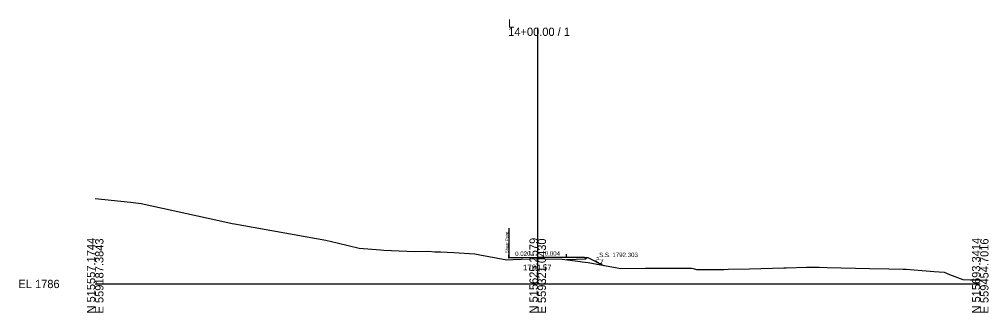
# Model space of a CAD drawing. Extents: x -26 to 1303, y -10 to 9545.
# Drawn here: x 974.3 to 1302.8, y 990.3 to 1089.6 of the extents above; entities that cross this region are included whole.
import ezdxf

# ---------------------------------------------------------------- set-up
doc = ezdxf.new("R2010")
doc.units = 0
for name, color, linetype in [('Exist Cross Section Cell', 7, 'Continuous'), ('Exist XS Center Line Elevation Label', 7, 'Continuous'), ('Exist XS Ground Line', 7, 'Continuous'), ('Prop XS Ditch Slope Text', 7, 'Continuous'), ('Prop XS Dump Level', 7, 'Continuous'), ('Prop XS EOT Tick Mark', 7, 'Continuous'), ('Prop XS Finish Grade', 7, 'Continuous'), ('Prop XS Finish Grade Earthwork', 7, 'Continuous'), ('Prop XS Finish Grade Paved Shoulder', 7, 'Continuous'), ('Prop XS Finish Grade Pavement', 7, 'Continuous'), ('Prop XS Pvmt Edge Slope', 7, 'Continuous'), ('Prop XS SE Text', 7, 'Continuous'), ('Prop XS Shear Point Label', 7, 'Continuous'), ('Prop XS SS Elevation Text', 7, 'Continuous'), ('Prop XS Subgrade Earthwork', 7, 'Continuous')]:
    doc.layers.add(name, color=color, linetype=linetype)

msp = doc.modelspace()

# ---------------------------------------------------------------- linework, layer by layer
at = {"layer": 'Exist Cross Section Cell'}
for p, q in [((1150, 1000), (1150, 1086.75)), ((1000, 1000), (1150, 1000)), ((1150, 1000), (1300, 1000))]:
    msp.add_line(p, q, dxfattribs=at)
at = {"layer": 'Exist XS Ground Line'}
for p, q in [((1000, 1028.92), (1011.97, 1027.67)), ((1011.97, 1027.67), (1015.62, 1027.19)), ((1015.62, 1027.19), (1041.86, 1021.5)), ((1041.86, 1021.5), (1046.44, 1020.5)), ((1046.44, 1020.5), (1047.27, 1020.34)), ((1047.27, 1020.34), (1078.22, 1014.87)), ((1078.22, 1014.87), (1082.07, 1013.97)), ((1082.07, 1013.97), (1089.48, 1012.15)), ((1089.48, 1012.15), (1096.66, 1011.53)), ((1096.66, 1011.53), (1097.82, 1011.47)), ((1097.82, 1011.47), (1108.2, 1010.99)), ((1108.2, 1010.99), (1112.94, 1011.05)), ((1112.94, 1011.05), (1115.15, 1010.92)), ((1115.15, 1010.92), (1117, 1010.85)), ((1117, 1010.85), (1121.56, 1010.62)), ((1121.56, 1010.62), (1128.7, 1010.22)), ((1128.7, 1010.22), (1130.41, 1009.9)), ((1130.41, 1009.9), (1139.56, 1008.22)), ((1139.56, 1008.22), (1141.69, 1008.33)), ((1141.69, 1008.33), (1150.22, 1008.57)), ((1150.22, 1008.57), (1152.45, 1008.52)), ((1152.45, 1008.52), (1158.25, 1008.44)), ((1158.25, 1008.44), (1164.53, 1007.62)), ((1164.53, 1007.62), (1165.12, 1007.52)), ((1165.12, 1007.52), (1167.05, 1007.21)), ((1167.05, 1007.21), (1178.22, 1005.27)), ((1186.46, 1005.31), (1189.15, 1005.35)), ((1189.15, 1005.35), (1191.52, 1005.35)), ((1191.52, 1005.35), (1194.72, 1005.35)), ((1194.72, 1005.35), (1202.13, 1005.35)), ((1202.13, 1005.35), (1202.65, 1005.19)), ((1221.78, 1005.09), (1233.45, 1005.45)), ((1233.45, 1005.45), (1234.19, 1005.47)), ((1234.19, 1005.47), (1241.11, 1005.67)), ((1241.11, 1005.67), (1243.07, 1005.73)), ((1243.07, 1005.73), (1245.37, 1005.64)), ((1245.37, 1005.64), (1248.1, 1005.6)), ((1248.1, 1005.6), (1262.5, 1005.26)), ((1178.22, 1005.27), (1186.46, 1005.31)), ((1202.65, 1005.19), (1203.77, 1004.94)), ((1203.77, 1004.94), (1213.13, 1004.9)), ((1213.13, 1004.9), (1214.59, 1004.98)), ((1214.59, 1004.98), (1221.78, 1005.09)), ((1262.5, 1005.26), (1268.97, 1005.11)), ((1268.97, 1005.11), (1273.83, 1005)), ((1273.83, 1005), (1274.92, 1005.01)), ((1274.92, 1005.01), (1284.36, 1004.22)), ((1284.36, 1004.22), (1287.8, 1003.95)), ((1287.8, 1003.95), (1289.53, 1003.24)), ((1289.53, 1003.24), (1294.11, 1001.48)), ((1294.11, 1001.48), (1296.61, 1001.43)), ((1296.61, 1001.43), (1297.71, 1001.4)), ((1297.71, 1001.4), (1300, 1001.35))]:
    msp.add_line(p, q, dxfattribs=at)
at = {"layer": 'Prop XS Dump Level'}
for p, q in [((1140, 1008.89), (1150, 1009.09)), ((1150, 1009.09), (1160, 1009.05))]:
    msp.add_line(p, q, dxfattribs=at)
at = {"layer": 'Prop XS EOT Tick Mark'}
for p, q in [((1140.26, 1008.9), (1140.26, 1009.9)), ((1159.74, 1009.05), (1159.74, 1010.05))]:
    msp.add_line(p, q, dxfattribs=at)
at = {"layer": 'Prop XS Finish Grade'}
msp.add_line((1165.72, 1009.03), (1166.74, 1008.96), dxfattribs=at)
at = {"layer": 'Prop XS Finish Grade Earthwork'}
for p, q in [((1166.74, 1008.96), (1166.98, 1008.95)), ((1166.98, 1008.95), (1172.27, 1006.3))]:
    msp.add_line(p, q, dxfattribs=at)
at = {"layer": 'Prop XS Finish Grade Paved Shoulder'}
msp.add_line((1159.74, 1009.05), (1165.72, 1009.03), dxfattribs=at)
at = {"layer": 'Prop XS Finish Grade Pavement'}
for p, q in [((1140.26, 1008.9), (1150, 1009.09)), ((1150, 1009.09), (1159.74, 1009.05))]:
    msp.add_line(p, q, dxfattribs=at)
at = {"layer": 'Prop XS Pvmt Edge Slope'}
msp.add_line((1165.72, 1009.03), (1166.26, 1008.48), dxfattribs=at)
at = {"layer": 'Prop XS Shear Point Label'}
msp.add_line((1140.26, 1018.83), (1140.26, 1008.9), dxfattribs=at)
at = {"layer": 'Prop XS Subgrade Earthwork'}
for p, q in [((1166.26, 1008.48), (1166.74, 1008.96)), ((1159.74, 1008.24), (1166.26, 1008.48))]:
    msp.add_line(p, q, dxfattribs=at)

# ---------------------------------------------------------------- texts
at = {"layer": 'Exist Cross Section Cell'}
for s, p in [('L', (1140, 1086.75)), ('14+00.00 / 1', (1140, 1083.95)), ('EL 1786', (974, 998.6))]:
    msp.add_text(s, height=2.8, dxfattribs=at).set_placement(p)
for s, p in [('N 515557.1744', (1000, 990)), ('E 559187.3843', (1002.8, 990)), ('N 515625.2579', (1150, 990)), ('E 559321.0430', (1152.8, 990)), ('N 515693.3414', (1300, 990)), ('E 559454.7016', (1302.8, 990))]:
    msp.add_text(s, height=2.8, rotation=90, dxfattribs=at).set_placement(p)
at = {"layer": 'Exist XS Center Line Elevation Label'}
msp.add_text('1794.57', height=2, dxfattribs=at).set_placement((1145.02, 1004.57))
at = {"layer": 'Prop XS Ditch Slope Text'}
msp.add_text('2:1', height=1.5, rotation=333.4349, dxfattribs=at).set_placement((1169.36, 1007.92))
at = {"layer": 'Prop XS Dump Level'}
for s, height, p in [('Eop', 0.3, (1130, 1009.67)), ('Case1', 0.04, (1163, 1008.82)), ('Eop', 0.3, (1170, 1006.4))]:
    msp.add_text(s, height=height, dxfattribs=at).set_placement(p)
at = {"layer": 'Prop XS SE Text'}
for s, rotation, p in [('0.020', 1.1458, (1142.38, 1009.44)), ('0.004', 359.7632, (1152.38, 1009.58))]:
    msp.add_text(s, height=1.5, rotation=rotation, dxfattribs=at).set_placement(p)
at = {"layer": 'Prop XS Shear Point Label'}
msp.add_text('Shear Point', height=1, rotation=90, dxfattribs=at).set_placement((1140.04, 1010.45))
at = {"layer": 'Prop XS SS Elevation Text'}
msp.add_text('S.S. 1792.303', height=1.5, dxfattribs=at).set_placement((1170.82, 1009.09))

doc.saveas('drawing.dxf')
